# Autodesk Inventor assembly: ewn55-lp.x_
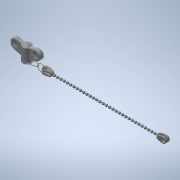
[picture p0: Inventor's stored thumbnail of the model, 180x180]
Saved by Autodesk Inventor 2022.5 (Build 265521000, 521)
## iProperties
Created: 2021-08
Part Number: ewn55-lp.x_
Material: 一般
Document SubType Name: Assembly
Designer: ImaoCorp
Sending System: SOLIDWORKS 2019-2019304
MC: AMD64
MC_MODEL: Intel64 Family 6 Model 60 Stepping 3, GenuineIntel
OS: Windows_NT
FRU: Parasolid Version 31.0, build 290,  9- 1-2019
FORMAT: text
GUISE: transmit
KEY: ewn55-lp
FILE: ewn55-lp.x_t
DATE: Wed Aug 11 15:06:01 2021
Author: ImaoCorp
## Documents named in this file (3)
- X:\14_SW2022-Inv2022\00_全2023-1023新製品(TCC)まで\e\ewn55-lp\EWN55-LP.iam
- X:\14_SW2022-Inv2022\00_全2023-1023新製品(TCC)まで\e\ewn55-lp\ewn55-lp_01.ipt
- X:\14_SW2022-Inv2022\00_全2023-1023新製品(TCC)まで\e\ewn55-lp\ewn55-lp_02.ipt
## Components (2 placed, 2 different names)
1. ewn55-lp_01
2. ewn55-lp_02
